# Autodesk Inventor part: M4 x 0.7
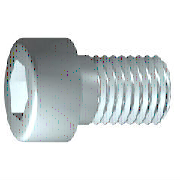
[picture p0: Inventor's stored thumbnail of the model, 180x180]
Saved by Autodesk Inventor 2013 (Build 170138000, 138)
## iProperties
IsCustomPart: 0
Created: 2015-10
Part Number: M4 x 0.7
Material: 강, 연강
Description: 6각머리 태핑 나사
Document SubType Name: Modeling
Standard: KS B 1003
Designer: mdu
Standards Organization: KS
Language: ko-KR
Size Designation: M 4 x 25
Categories: <MemberInstance><Categories><Category DisplayName="조임쇠" InternalName="e4da775c-781d-43d5-af7c-5136215cf5a6" Mnemonic="FSTN"><Category DisplayName="볼트" InternalN
Density: 1 g/cm^3
Author: mdu
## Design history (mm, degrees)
sketch "스케치1"
  geometry: L1 (-1, 0)-(25, 0); L2 (25, 0)-(25, 2); L3 (25, 2)-(1.75, 2); L4 (1.75, 2)-(1.32, 2); L5 (1.32, 2)-(0, 2); L6 (0, 2)-(0, 3.5); L7 (0, 3.5)-(-4, 3.5); L8 (-4, 3.5)-(-4, 1.732); L9 (-4, 1.732)-(-2, 1.732); L10 (-2, 1.732)-(-1, 0); L11 (-9.8, 0)-(30.8, 0) reference; L12 (0, -0.7)-(0, 4.2) reference; L13 (1.75, 2)-(0, 2)
  constraints: 22 end point, 6 parallel, 2 collinear, 2 perpendicular, 1 horizontal, 1 point on line
  dimensions: "d1" = 23.25 distance from line of L3.end L2 (= GEL); "d2" = 0.42952 distance of L4.end L3.end (computed from GAL); "d3" = 4 distance between parallel lines of L8 L6 (= KOH); "d4" = 2 distance of L8.end L9.end (= INTI); "d5" = 60 deg angle of L10 L1; "d6" = 4 diameter of L3 L1 (= GD); "d7" = 4 diameter of L5 L1 (= BDM); "d8" = 3.4641 diameter of L9 L1 (= 1.1547 x SW); "d9" = 7 diameter of L7 L1 (= KOD); "d26" = 25 distance between parallel lines of L12 L2 (= NLG)
revolve "본체" sketch "스케치1" stored, may be unused: angle "d10" = 90 deg
sketch "스케치2"
  geometry: L1 (0, -4.9)-(0, 4.9) reference; L2 (-4.9, 0)-(4.9, 0) reference; L3 (1.732, 0)-(0.866, -1.5); L4 (0.866, -1.5)-(-0.866, -1.5); L5 (-0.866, -1.5)-(-1.732, 0); L6 (-1.732, 0)-(-0.866, 1.5); L7 (-0.866, 1.5)-(0.866, 1.5); L8 (0.866, 1.5)-(1.732, 0); 2 further points
  constraints: 12 end point, 1 coincident, 1 horizontal alignment, 1 point on line, 12 other
extrude "슬롯" join sketch "스케치2" stored distance "d11" = 10; taper "d12" = 0 deg
workplane "Work Plane1"
fillet "Fillet2" dims "d30" = 0.1 (= R)
body "Solid1"
fillet "모깎기1" dims "d17" = 0.4 (= RR)
feature "스레드" dims "d13" = 23.25 (= GEL), "d14" = 0
chamfer "모따기1" distance "d15" = 0.42941 (= -0.5 x SPD + 0.5 x GD); stored, may be unused: second distance "d16" = 0.42941 (= GUL), angle "d27" = 45 deg
other parameters: "GD" = 4 (= NND) [user parameter; used in 2 equation terms], "NLG" = 25 [user parameter; used in 1 equation term], "GEL" = 23.25 [user parameter; used in 2 equation terms], "KOD" = 7 [user parameter; used in 1 equation term], "KOH" = 4 [user parameter; used in 1 equation term], "INTI" = 2 [user parameter; used in 1 equation term], "GAL" = 0.42941 (= 0.61345 x PTC) [user parameter; used in 1 equation term], "GUL" = 0.42941 (= 0.61345 x PTC) [user parameter; used in 1 equation term], "BDM" = 4 (= NND) [user parameter; used in 1 equation term], "SW" = 3 [user parameter; used in 2 equation terms], "RR" = 0.4 [user parameter; used in 1 equation term], "SPD" = 3.14117 (= NND - 1.2269 x PTC) [user parameter; used in 1 equation term], "d19" = 0, "d28" = 0, "d29" = 0, "R" = 0.1 [user parameter; used in 1 equation term], "PHH" = 0.2 [user parameter], "GD1" = 3.14117 (= THREADDIA - 1.2269 x PTC) [user parameter], "THREADDIA" = 4 [user parameter; used in 1 equation term], "FAWI" = 45 deg [user parameter], "TPU" = 14.28571 (computed from PTC) [user parameter], "PTC" = 0.7 [user parameter; used in 5 equation terms], "NND" = 4 [user parameter; used in 3 equation terms], "TOA" = 30 deg [user parameter], "E0" = 3.465 (= 1.155 x SW) [user parameter]
